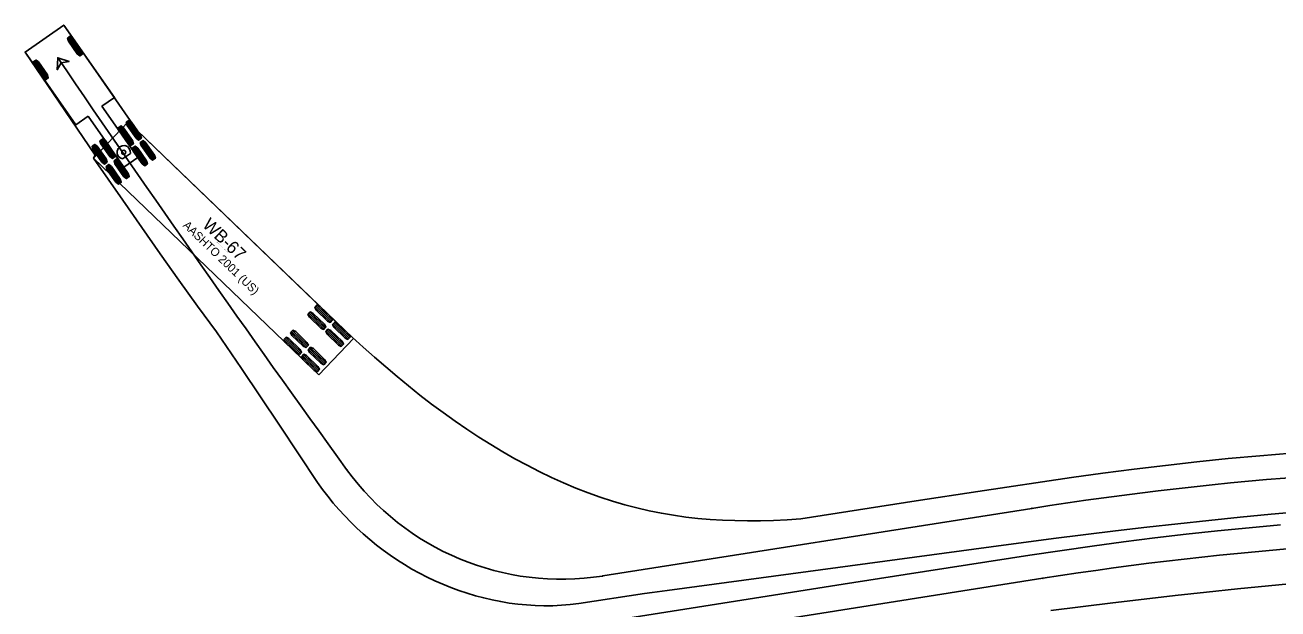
# Model space of a CAD drawing. Extents: x 1639988 to 1641860, y 841974 to 844187.
# Drawn here: x 1640966.8 to 1641179.4, y 842690.9 to 842789.8 of the extents above; entities that cross this region are included whole.
import ezdxf

# ---------------------------------------------------------------- set-up
doc = ezdxf.new("R2010")
doc.units = 0
doc.layers.add('Scratch_Level_1', color=7, linetype='Continuous')

msp = doc.modelspace()

# ---------------------------------------------------------------- linework, layer by layer
at = {"layer": 'Scratch_Level_1'}
for p, q in [((1640973.35, 842789.83), (1640966.8, 842785.25)), ((1640981.95, 842777.54), (1640973.35, 842789.83)), ((1640974.24, 842787.8), (1640976.31, 842784.77)), ((1640974.43, 842787.93), (1640976.5, 842784.9)), ((1640974.05, 842787.67), (1640976.12, 842784.64)), ((1640966.8, 842785.25), (1640975.39, 842772.95)), ((1640966.8, 842785.25), (1640966.8, 842785.25)), ((1640968.24, 842783.62), (1640970.31, 842780.59)), ((1640968.43, 842783.75), (1640970.5, 842780.72)), ((1640968.62, 842783.88), (1640970.68, 842780.85)), ((1640979.85, 842776.07), (1640981.95, 842777.54)), ((1640985.91, 842767.39), (1640979.85, 842776.07)), ((1640975.39, 842772.95), (1640977.5, 842774.42)), ((1640977.5, 842774.42), (1640983.56, 842765.75)), ((1640984.32, 842773.42), (1640978.43, 842767.3)), ((1640984.01, 842773.39), (1640986.11, 842770.38)), ((1640984.2, 842773.52), (1640986.3, 842770.51)), ((1641022.53, 842736.69), (1640984.32, 842773.42)), ((1640984.39, 842773.65), (1640986.49, 842770.65)), ((1640982.66, 842772.44), (1640984.76, 842769.44)), ((1640982.85, 842772.57), (1640984.95, 842769.57)), ((1640983.04, 842772.7), (1640985.14, 842769.7)), ((1640978.21, 842769.33), (1640980.31, 842766.32)), ((1640978.4, 842769.46), (1640980.5, 842766.46)), ((1640978.58, 842769.59), (1640980.68, 842766.59)), ((1640979.56, 842770.27), (1640981.66, 842767.27)), ((1640979.75, 842770.41), (1640981.85, 842767.4)), ((1640979.94, 842770.54), (1640982.04, 842767.53)), ((1640985.05, 842769.03), (1640987.15, 842766.02)), ((1640985.24, 842769.16), (1640987.34, 842766.15)), ((1640985.42, 842769.29), (1640987.52, 842766.29)), ((1640986.4, 842769.97), (1640988.5, 842766.97)), ((1640986.59, 842770.1), (1640988.69, 842767.1)), ((1640986.78, 842770.24), (1640988.88, 842767.23)), ((1640978.43, 842767.3), (1641016.64, 842730.56)), ((1640978.43, 842767.3), (1640978.43, 842767.3)), ((1640981.95, 842766.86), (1640984.05, 842763.85)), ((1640982.13, 842766.99), (1640984.24, 842763.99)), ((1640982.32, 842767.12), (1640984.42, 842764.12)), ((1640983.34, 842767.15), (1640984.67, 842768.08)), ((1640983.56, 842765.75), (1640985.91, 842767.39)), ((1640980.59, 842765.91), (1640982.7, 842762.91)), ((1640980.78, 842766.05), (1640982.88, 842763.04)), ((1640980.97, 842766.18), (1640983.07, 842763.17)), ((1641015, 842741), (1641017.65, 842738.46)), ((1641015.16, 842741.17), (1641017.8, 842738.63)), ((1641015.99, 842742.03), (1641018.63, 842739.49)), ((1641016.15, 842742.19), (1641018.79, 842739.65)), ((1641016.31, 842742.36), (1641018.95, 842739.82)), ((1641014.84, 842740.84), (1641017.49, 842738.3)), ((1641018.99, 842739.14), (1641021.63, 842736.6)), ((1641019.15, 842739.31), (1641021.79, 842736.76)), ((1641019.31, 842739.47), (1641021.95, 842736.93)), ((1641011.05, 842736.89), (1641013.69, 842734.35)), ((1641011.88, 842737.75), (1641014.52, 842735.21)), ((1641012.03, 842737.92), (1641014.68, 842735.37)), ((1641012.19, 842738.08), (1641014.84, 842735.54)), ((1641017.85, 842737.95), (1641020.49, 842735.41)), ((1641018.01, 842738.12), (1641020.65, 842735.57)), ((1641018.17, 842738.28), (1641020.81, 842735.74)), ((1641010.73, 842736.56), (1641013.37, 842734.02)), ((1641010.89, 842736.73), (1641013.53, 842734.19)), ((1641014.88, 842734.86), (1641017.52, 842732.32)), ((1641015.04, 842735.03), (1641017.68, 842732.49)), ((1641015.2, 842735.19), (1641017.84, 842732.65)), ((1641016.64, 842730.56), (1641022.53, 842736.69)), ((1641013.74, 842733.67), (1641016.38, 842731.13)), ((1641013.89, 842733.84), (1641016.54, 842731.3)), ((1641014.05, 842734), (1641016.7, 842731.46)), ((1641137.63, 842707.93), (1641064.81, 842696.47)), ((1641139.5, 842696.08), (1641051.19, 842682.18))]:
    msp.add_line(p, q, dxfattribs=at)
for points in [[(1641183.52, 842707.41), (1641178.24, 842706.93), (1641172.96, 842706.42), (1641167.68, 842705.88), (1641162.4, 842705.31), (1641157.12, 842704.72), (1641151.84, 842704.1), (1641141.28, 842702.8), (1641130.73, 842701.42), (1641075.77, 842693.99), (1641073.22, 842693.66), (1641071.92, 842693.52), (1641060.77, 842691.79), (1641059.29, 842691.62), (1641057.81, 842691.5), (1641056.33, 842691.44), (1641054.85, 842691.43), (1641053.37, 842691.47), (1641051.9, 842691.56), (1641050.43, 842691.7), (1641048.97, 842691.89), (1641047.52, 842692.13), (1641046.07, 842692.42), (1641044.64, 842692.75), (1641043.22, 842693.12), (1641041.82, 842693.54), (1641040.42, 842694.01), (1641039.05, 842694.51), (1641037.69, 842695.06), (1641036.35, 842695.65), (1641035.03, 842696.27), (1641033.73, 842696.94), (1641032.45, 842697.65), (1641031.2, 842698.39), (1641029.97, 842699.17), (1641028.76, 842699.98), (1641027.58, 842700.83), (1641026.42, 842701.72), (1641025.29, 842702.64), (1641024.19, 842703.59), (1641023.11, 842704.57), (1641022.06, 842705.59), (1641021.05, 842706.64), (1641020.06, 842707.72), (1641019.1, 842708.83), (1641018.18, 842709.97), (1641017.28, 842711.14), (1641016.42, 842712.34), (1641009.95, 842722.04), (1641003.51, 842731.61), (1640999.28, 842737.83), (1640996.06, 842742.21), (1640992.88, 842746.62), (1640989.72, 842751.06), (1640986.59, 842755.52), (1640983.37, 842760.14), (1640978.43, 842767.3), (1640978.71, 842767.78), (1640972.58, 842776.75), (1640966.8, 842785.25), (1640973.35, 842789.83), (1640979.25, 842781.41), (1640985.67, 842772.17), (1640985.88, 842771.93), (1641020.43, 842738.71), (1641022.31, 842736.96), (1641024.19, 842735.23), (1641026.08, 842733.54), (1641027.99, 842731.89), (1641029.92, 842730.26), (1641031.86, 842728.67), (1641033.81, 842727.12), (1641035.78, 842725.61), (1641037.76, 842724.15), (1641039.76, 842722.72), (1641041.77, 842721.34), (1641043.79, 842720.02), (1641045.82, 842718.74), (1641047.86, 842717.51), (1641049.91, 842716.34), (1641051.97, 842715.23), (1641054.04, 842714.17), (1641056.11, 842713.18), (1641058.18, 842712.25), (1641060.26, 842711.38), (1641062.33, 842710.58), (1641064.41, 842709.84), (1641066.49, 842709.16), (1641068.56, 842708.55), (1641070.63, 842708.01), (1641072.71, 842707.53), (1641074.78, 842707.11), (1641076.85, 842706.76), (1641078.92, 842706.46), (1641080.98, 842706.23), (1641083.05, 842706.05), (1641085.12, 842705.93), (1641087.23, 842705.85), (1641089.38, 842705.82), (1641091.58, 842705.83), (1641093.82, 842705.89), (1641096.1, 842705.99), (1641098.41, 842706.13), (1641118.03, 842709.19), (1641128.47, 842710.79), (1641144.36, 842713.14), (1641149.66, 842713.88), (1641154.97, 842714.57), (1641160.29, 842715.22), (1641165.62, 842715.81), (1641170.96, 842716.36), (1641176.3, 842716.86), (1641181.65, 842717.31)], [(1640972.37, 842784.26), (1640972.26, 842782.26), (1640972.93, 842783.43), (1640974.27, 842783.64), (1640972.37, 842784.26)], [(1641066.92, 842689), (1641105.61, 842695.11), (1641116.13, 842696.75), (1641126.71, 842698.38), (1641137.29, 842699.98), (1641147.89, 842701.52), (1641153.19, 842702.25), (1641158.51, 842702.92), (1641163.83, 842703.55), (1641169.16, 842704.12), (1641174.5, 842704.65), (1641179.85, 842705.12)], [(1641183.07, 842695.3), (1641177.79, 842694.81), (1641172.52, 842694.3), (1641167.24, 842693.75), (1641161.96, 842693.17), (1641156.68, 842692.57), (1641151.4, 842691.94), (1641140.84, 842690.63)]]:
    msp.add_lwpolyline(points, dxfattribs=at)
for points in [[(1640974.01, 842787.64), (1640974.48, 842787.96), (1640974.91, 842787.63), (1640976.4, 842785.45), (1640976.54, 842784.93), (1640976.07, 842784.61), (1640975.64, 842784.94), (1640974.15, 842787.12)], [(1640968.19, 842783.59), (1640968.67, 842783.91), (1640969.1, 842783.59), (1640970.58, 842781.4), (1640970.73, 842780.88), (1640970.26, 842780.56), (1640969.83, 842780.89), (1640968.34, 842783.07)], [(1640972.37, 842784.26), (1640972.26, 842782.26), (1640972.93, 842783.43), (1640974.27, 842783.64)], [(1640983.97, 842773.36), (1640984.43, 842773.68), (1640984.87, 842773.36), (1640986.38, 842771.2), (1640986.54, 842770.68), (1640986.07, 842770.35), (1640985.63, 842770.67), (1640984.12, 842772.84)], [(1640982.61, 842772.41), (1640983.08, 842772.74), (1640983.52, 842772.42), (1640985.03, 842770.25), (1640985.18, 842769.73), (1640984.71, 842769.4), (1640984.28, 842769.73), (1640982.77, 842771.89)], [(1640978.16, 842769.3), (1640978.63, 842769.62), (1640979.06, 842769.3), (1640980.58, 842767.14), (1640980.73, 842766.62), (1640980.26, 842766.29), (1640979.83, 842766.61), (1640978.31, 842768.78)], [(1640979.51, 842770.24), (1640979.98, 842770.57), (1640980.42, 842770.25), (1640981.93, 842768.08), (1640982.08, 842767.56), (1640981.61, 842767.24), (1640981.18, 842767.56), (1640979.67, 842769.72)], [(1640985, 842768.99), (1640985.47, 842769.32), (1640985.91, 842769), (1640987.42, 842766.84), (1640987.57, 842766.32), (1640987.1, 842765.99), (1640986.67, 842766.31), (1640985.15, 842768.48)], [(1640986.35, 842769.94), (1640986.82, 842770.27), (1640987.26, 842769.95), (1640988.77, 842767.78), (1640988.92, 842767.26), (1640988.45, 842766.94), (1640988.02, 842767.26), (1640986.51, 842769.42)], [(1640981.9, 842766.83), (1640982.37, 842767.15), (1640982.8, 842766.83), (1640984.32, 842764.67), (1640984.47, 842764.15), (1640984, 842763.82), (1640983.57, 842764.14), (1640982.05, 842766.31)], [(1640980.55, 842765.88), (1640981.02, 842766.21), (1640981.45, 842765.89), (1640982.96, 842763.72), (1640983.12, 842763.2), (1640982.65, 842762.88), (1640982.21, 842763.2), (1640980.7, 842765.36)], [(1641014.8, 842740.8), (1641015.2, 842741.21), (1641015.69, 842740.98), (1641017.59, 842739.15), (1641017.84, 842738.67), (1641017.45, 842738.26), (1641016.96, 842738.49), (1641015.06, 842740.32)], [(1641015.95, 842741.99), (1641016.34, 842742.4), (1641016.83, 842742.17), (1641018.74, 842740.34), (1641018.99, 842739.86), (1641018.59, 842739.45), (1641018.1, 842739.68), (1641016.2, 842741.51)], [(1641018.95, 842739.1), (1641019.35, 842739.51), (1641019.84, 842739.28), (1641021.74, 842737.45), (1641021.99, 842736.97), (1641021.59, 842736.56), (1641021.11, 842736.79), (1641019.2, 842738.62)], [(1641010.69, 842736.52), (1641011.09, 842736.93), (1641011.58, 842736.7), (1641013.48, 842734.87), (1641013.73, 842734.39), (1641013.34, 842733.98), (1641012.85, 842734.21), (1641010.94, 842736.04)], [(1641011.84, 842737.71), (1641012.23, 842738.12), (1641012.72, 842737.89), (1641014.62, 842736.06), (1641014.88, 842735.58), (1641014.48, 842735.17), (1641013.99, 842735.4), (1641012.09, 842737.23)], [(1641017.81, 842737.91), (1641018.2, 842738.32), (1641018.69, 842738.09), (1641020.6, 842736.26), (1641020.85, 842735.78), (1641020.45, 842735.37), (1641019.96, 842735.6), (1641018.06, 842737.43)], [(1641014.84, 842734.82), (1641015.24, 842735.23), (1641015.73, 842735), (1641017.63, 842733.17), (1641017.88, 842732.69), (1641017.48, 842732.28), (1641016.99, 842732.51), (1641015.09, 842734.34)], [(1641013.7, 842733.63), (1641014.09, 842734.04), (1641014.58, 842733.81), (1641016.48, 842731.98), (1641016.74, 842731.5), (1641016.34, 842731.09), (1641015.85, 842731.32), (1641013.95, 842733.15)]]:
    msp.add_lwpolyline(points, close=True, dxfattribs=at)
for centre, radius in [((1640972.37, 842784.26), 0.0417), ((1640983.54, 842768.28), 0.34), ((1641021.36, 842714.53), 0.0417), ((1641021.36, 842714.53), 0.0417), ((1641137.63, 842707.93), 0.0417), ((1641137.63, 842707.93), 0.0417), ((1641064.81, 842696.47), 0.0417), ((1641064.81, 842696.47), 0.0417), ((1641139.5, 842696.08), 0.0417), ((1641139.5, 842696.08), 0.0417)]:
    msp.add_circle(centre, radius, dxfattribs=at)
for centre, radius, start, end in [((1643441.46, 844467.03), 2988, 214.27571, 215.90998), ((1640983.54, 842768.28), 1.14, 349.9594, 259.9594), ((1641057.81, 842740.92), 45, 215.91, 278.9449), ((1641228.74, 842129.06), 586, 89.28137, 98.94492), ((1641228.74, 842129.06), 574, 89.28137, 98.94492)]:
    msp.add_arc(centre, radius, start, end, dxfattribs=at)

# ---------------------------------------------------------------- texts
for s, height, p in [('AASHTO 2001 (US)', 1.4167, (1640993.48, 842755.77)), ('WB-67', 2.125, (1640996.77, 842755.8)), ('(c) 2019 Transoft Solutions, Inc. All rights reserved.', 0.085, (1640999.2, 842753.16))]:
    msp.add_text(s, height=height, rotation=316.1269, dxfattribs=at).set_placement(p)

doc.saveas('drawing.dxf')
